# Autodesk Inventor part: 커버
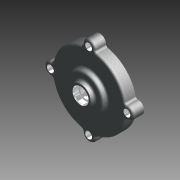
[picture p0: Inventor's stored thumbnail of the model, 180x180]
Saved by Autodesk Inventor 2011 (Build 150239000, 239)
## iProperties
Created: 2012-05
Part Number: 커버
Document SubType Name: 모델링
Designer: SeoGD™
Material: 알루미늄-6061
Mass: 196.659 g
Surface Area: 278.607 cm^2
Volume: 72.5678 cm^3
Density: 2.71 g/cm^3
변환 표준: STEP AP214IS
파일 이름: C:\Users\SeoGD\Desktop\?쒗뿕\而ㅻ쾭-1.stp
전처리기: Build: 253, Release: 2010 SP1 - Date: Wed 07/29/2009
전송 단위: 밀리미터
불확실성: 0.01
Author: SeoGD™
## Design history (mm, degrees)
sketch "스케치1"
  geometry: L1 (0, 0)-(0, 26); L2 (50, 0)-(50, 15); L3 (50, 15)-(25, 15); L4 (25, 15)-(25, 21); L5 (25, 21)-(15, 21); L6 (15, 21)-(13.66, 26); L7 (13.66, 26)-(10, 26); L8 (50, 0)-(45, 0); L9 (45, 0)-(45, 10); L10 (45, 10)-(14.5, 10); L11 (14.5, 10)-(13.266, 3); L12 (13.266, 3)-(11, 3); L13 (11, 3)-(11, 16); L14 (11, 16)-(7.5, 16); L15 (7.5, 16)-(7.5, 19); L16 (7.5, 19)-(10, 19); L17 (10, 19)-(10, 26)
  constraints: 34 end point, 10 parallel, 2 perpendicular, 2 point on line, 1 vertical
  dimensions: "d11" = 100 diameter of L2 L1; "d12" = 22 diameter of L13 L1; "d13" = 90 diameter of L9 L1; "d14" = 15 distance between parallel lines of L3 L8; "d15" = 10 distance between parallel lines of L8 L10; "d16" = 29 diameter of L10.end L1; "d17" = 100 deg angle of L11 L10; "d18" = 7 distance between parallel lines of L12 L10; "d19" = 13 distance between parallel lines of L14 L12; "d20" = 3 distance between parallel lines of L16 L14; "d21" = 15 diameter of L15 L1; "d22" = 20 diameter of L17 L1; "d23" = 30 diameter of L5.end L1; "d24" = 6 distance between parallel lines of L5 L3; "d25" = 50 diameter of L4 L1; "d26" = 105 deg angle of L5 L6; "d50" = 26 distance of L1.start L1.end
revolve "회전1" sketch "스케치1" stored, may be unused: angle "d27" = 90 deg
sketch "스케치2" dims "d29" = 104
  geometry: A1 r 8.5 centre (0, 52) between (8.074, 49.344) and (-8.074, 49.344); A2 r 50 centre (0, 0) between (-8.074, 49.344) and (8.074, 49.344) reference; 2 further points
  constraints: 4 point on circle, 2 vertical alignment, 1 centre point, 1 coincident, 2 other
  dimensions: "d28" = 17 diameter of A1
extrude "돌출1" join sketch "스케치2" stored distance "d30" = 10; taper "d31" = 0 deg
fillet "모깎기3" dims "d32" = 3
fillet "모깎기4" dims "d45" = 3, "d46" = 0.2
chamfer "모따기1" distance "d47" = 1; stored, may be unused: second distance "d48" = 2, angle "d49" = 45 deg
hole "구멍2" diameter "d38" = 5.5; stored, may be unused: countersink angle "d42" = 90 deg, drill point angle "d44" = 118 deg; dims "d36" = 10, "d37" = 10, "d39" = 6, "d40" = 9.5, "d41" = 5.4, "d43" = 8
node "솔리드1"
node "솔리드 본체"
node "곡면 본체"
pattern_circular "원형 패턴1" dims angle "d34" = 360 deg
pattern_circular "원형 패턴2" dims angle "d52" = 360 deg
node "솔리드2"
